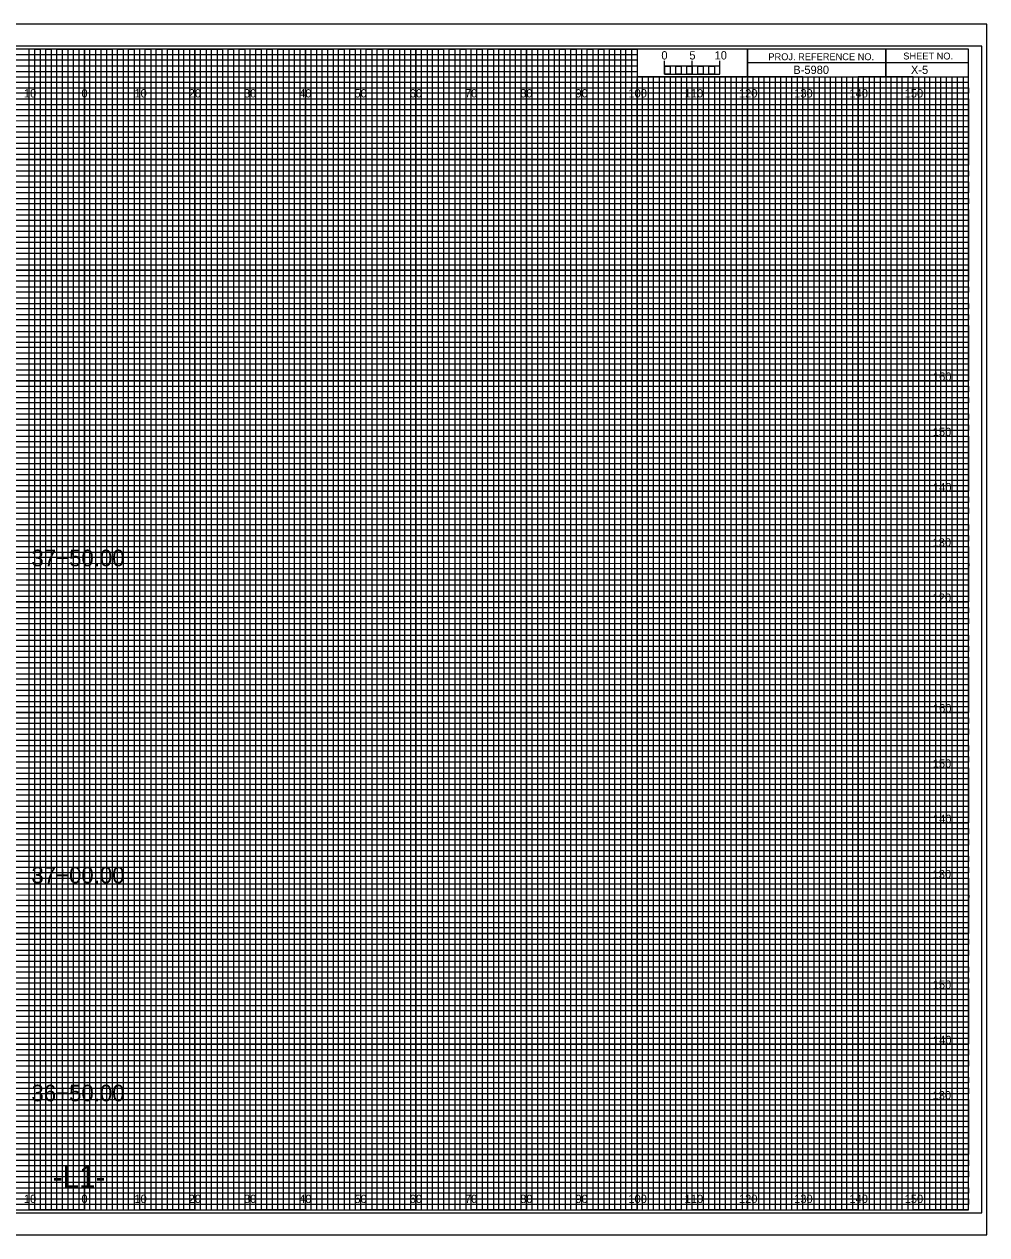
# Model space of a CAD drawing. Extents: x -13 to 323, y -5 to 3294.
# Drawn here: x 149.1 to 323.3, y 875.5 to 1094.5 of the extents above; entities that cross this region are included whole.
import ezdxf

# ---------------------------------------------------------------- set-up
doc = ezdxf.new("R2010")
doc.units = 0
for name, color, linetype in [('Prop XS Alignment Label', 7, 'Continuous'), ('Prop XS Bar Scale Labels', 7, 'Continuous'), ('Prop XS Elevation Labels', 7, 'Continuous'), ('Prop XS Offset Labels', 7, 'Continuous'), ('Prop XS Project Number', 7, 'Continuous'), ('Prop XS Sheet Number', 7, 'Continuous'), ('Prop XS Station Labels', 7, 'Continuous'), ('Sheet Cross Section CELL', 7, 'Continuous'), ('Sheet Cross Section Grid Major CELL', 7, 'Continuous'), ('Sheet Cross Section Grid Middle CELL', 7, 'Continuous'), ('Sheet Cross Section Grid Minor 1 CELL', 7, 'Continuous'), ('Sheet Cross Section Grid Minor 2 CELL', 7, 'Continuous'), ('Sheet Cross Section Scale CELL', 7, 'Continuous'), ('Sheet Cutting Line CELL', 7, 'Continuous'), ('Sheet DOT Grid CELL', 7, 'Continuous'), ('Sheet Plot Border Inside CELL', 7, 'Continuous'), ('Sheet Plot Border Outside CELL', 7, 'Continuous')]:
    doc.layers.add(name, color=color, linetype=linetype)

msp = doc.modelspace()

# ---------------------------------------------------------------- linework, layer by layer
at = {"layer": 'Sheet Cross Section CELL'}
for p, q in [((305, 1090), (305, 1085)), ((305, 1085), (305, 1090)), ((280, 1087.5), (280, 1085)), ((320, 1087.49), (280, 1087.49)), ((280, 1085), (320, 1085))]:
    msp.add_line(p, q, dxfattribs=at)
for points in [[(320, 1090), (0, 1090), (0, 880), (320, 880)], [(280, 1090), (260, 1090), (260, 1085.03), (280, 1085.03)], [(320, 1090), (280, 1090), (280, 1085), (320, 1085)]]:
    msp.add_lwpolyline(points, close=True, dxfattribs=at)
at = {"layer": 'Sheet Cross Section Grid Major CELL'}
for p, q in [((150, 1090), (140, 1090)), ((150, 880), (150, 1090)), ((170, 1090), (160, 1090)), ((160, 1090), (160, 880)), ((170, 880), (170, 1090)), ((190, 1090), (180, 1090)), ((180, 1090), (180, 880)), ((190, 880), (190, 1090)), ((210, 1090), (200, 1090)), ((200, 1090), (200, 880)), ((210, 880), (210, 1090)), ((230, 1090), (220, 1090)), ((220, 1090), (220, 880)), ((230, 880), (230, 1090)), ((250, 1090), (240, 1090)), ((240, 1090), (240, 880)), ((250, 880), (250, 1090)), ((260, 1090), (260, 880)), ((270, 880), (270, 1085)), ((290, 1085), (280, 1085)), ((280, 1085), (280, 880)), ((290, 880), (290, 1085)), ((310, 1085), (300, 1085)), ((300, 1085), (300, 880)), ((310, 880), (310, 1085)), ((160, 880), (150, 880)), ((180, 880), (170, 880)), ((200, 880), (190, 880)), ((220, 880), (210, 880)), ((240, 880), (230, 880)), ((260, 880), (250, 880)), ((280, 880), (270, 880)), ((300, 880), (290, 880)), ((320, 880), (310, 880)), ((320, 880), (320, 880))]:
    msp.add_line(p, q, dxfattribs=at)
for points in [[(0, 1080), (320, 1080), (320, 1070), (0, 1070)], [(0, 1060), (320, 1060), (320, 1050), (0, 1050)], [(0, 1040), (320, 1040), (320, 1030), (0, 1030)], [(0, 1020), (320, 1020), (320, 1010), (0, 1010)], [(0, 1000), (320, 1000), (320, 990), (0, 990)], [(0, 980), (320, 980), (320, 970), (0, 970)], [(0, 960), (320, 960), (320, 950), (0, 950)], [(0, 940), (320, 940), (320, 930), (0, 930)], [(0, 920), (320, 920), (320, 910), (0, 910)], [(0, 900), (320, 900), (320, 890), (0, 890)]]:
    msp.add_lwpolyline(points, dxfattribs=at)
at = {"layer": 'Sheet Cross Section Grid Middle CELL'}
for points in [[(145, 880), (155, 880), (155, 1090), (165, 1090), (165, 880), (175, 880), (175, 1090), (185, 1090), (185, 880), (195, 880), (195, 1090), (205, 1090), (205, 880), (215, 880), (215, 1090), (225, 1090), (225, 880), (235, 880), (235, 1090), (245, 1090), (245, 880), (255, 880), (255, 1090), (259.93, 1090), (260, 1090), (260, 1085), (264.99, 1085), (264.99, 880), (275, 880), (275, 1085), (285, 1085), (285, 880), (295, 880), (295, 1085), (305, 1085), (305, 880), (315, 880), (315, 1085)], [(0, 1085), (275, 1085)], [(0, 1065), (320, 1065), (320, 1075), (0, 1075)], [(0, 1045), (320, 1045), (320, 1055), (0, 1055)], [(0, 1025), (320, 1025), (320, 1035), (0, 1035)], [(0, 1005), (320, 1005), (320, 1015), (0, 1015)], [(0, 985), (320, 985), (320, 995), (0, 995)], [(0, 965), (320, 965), (320, 975), (0, 975)], [(0, 945), (320, 945), (320, 955), (0, 955)], [(0, 925), (320, 925), (320, 935), (0, 935)], [(0, 905), (320, 905), (320, 915), (0, 915)], [(0, 885), (320, 885), (320, 895), (0, 895)]]:
    msp.add_lwpolyline(points, dxfattribs=at)
at = {"layer": 'Sheet Cross Section Grid Minor 1 CELL'}
for p, q in [((0, 1089), (260, 1089)), ((260, 1089), (260, 1087.98)), ((260, 1087.98), (0, 1087.98)), ((0, 1087), (260, 1087)), ((260, 1087), (260, 1085.89)), ((260, 1085.89), (0, 1085.89)), ((0, 1084), (320, 1084))]:
    msp.add_line(p, q, dxfattribs=at)
for points in [[(0, 1083), (270, 1083), (320, 1083), (320, 1082), (0, 1082)], [(0, 1081), (320, 1081), (320, 1079), (0, 1079)], [(0, 1078), (320, 1078), (320, 1077), (0, 1076.98)], [(0, 1076), (320, 1076), (320, 1074), (0, 1074)], [(0, 1073), (320, 1073), (320, 1072), (0, 1072)], [(0, 1071), (320, 1071), (320, 1069), (0, 1069)], [(0, 1068), (320, 1068), (320, 1067), (0, 1067)], [(0, 1066), (320, 1066), (320, 1064), (0, 1064)], [(0, 1063), (320, 1063), (320, 1062), (0, 1062)], [(0, 1061), (320, 1061), (320, 1059), (0, 1059)], [(0, 1058), (320, 1058), (320, 1057), (0, 1057)], [(0, 1056), (320, 1056), (320, 1053.95), (320, 1053), (320, 1052), (0, 1052)], [(0, 1054), (320, 1054), (320, 1053), (0, 1053)], [(0, 1051), (320, 1051), (320, 1049), (0, 1049.03)], [(0, 1049.03), (320, 1049), (320, 1048), (0, 1048)], [(0, 1047), (320, 1047), (320, 1046), (0, 1046)], [(0, 1044), (320, 1044), (320, 1043), (0, 1043)], [(0, 1042), (320, 1042), (320, 1041), (0, 1041)], [(-0.07, 1038.89), (320, 1038.89), (320, 1037.88), (-0.07, 1037.88)], [(0, 1037), (320, 1037), (320, 1036), (0, 1036)], [(0, 1034), (320, 1034), (320, 1033), (0, 1033)], [(0, 1032), (320, 1032), (320, 1031), (0, 1031)], [(0, 1029), (320, 1029), (320, 1028), (0, 1028)], [(0, 1027), (320, 1027), (320, 1026), (0, 1026)], [(0, 1024), (320, 1024), (320, 1023), (0, 1023)], [(0, 1022), (320, 1022), (320, 1021), (0, 1021)], [(0, 1019), (320, 1019), (319.99, 1017.98), (0, 1018)], [(0, 1017), (320, 1017), (320, 1016), (0, 1016)], [(0, 1014), (320, 1014), (320, 1013), (0, 1013)], [(0, 1012), (320, 1012), (320, 1011), (0, 1011)], [(0, 1009), (320, 1009), (320, 1008), (0, 1008)], [(0, 1007), (320, 1007), (320, 1006), (0, 1006)], [(0, 1004), (320, 1004), (320, 1003), (0, 1003)], [(0, 1002), (320, 1002), (320, 1001), (0, 1001)], [(0, 999), (320, 999), (320, 998), (0, 998)], [(0, 996.99), (320.07, 996.91), (320, 996), (0, 996)], [(0, 994), (320, 994), (320, 993), (0, 993)], [(0, 992), (320, 992), (320, 991), (0, 991)], [(0, 989), (320, 989), (320, 988), (0, 988)], [(0, 987), (320, 987), (320, 986), (0, 986)], [(0, 984), (320, 984), (320, 983), (0, 983)], [(0, 982), (320, 982), (320, 981), (0, 981)], [(0, 979), (320, 979), (320, 978), (0, 978)], [(0, 977), (320, 977), (320, 976), (0, 976)], [(0, 974), (320, 974), (320, 973), (0, 973)], [(0, 972), (320, 972), (320, 971), (0, 971)], [(0, 969), (320, 969), (320, 968), (0, 968)], [(0, 967), (320, 967), (320, 966), (0, 966)], [(0, 964), (320, 964), (320, 963), (0, 963)], [(0, 962), (320, 962), (320, 961), (0, 961)], [(0, 959), (320, 959), (319.99, 957.98), (0, 958)], [(0, 957), (320, 957), (320, 956), (0, 956)], [(0, 954), (320, 954), (320, 953), (0, 953)], [(0, 952), (320, 952), (320, 951), (0, 951)], [(0, 949), (320, 949), (320, 948), (0, 948)], [(0, 947), (320, 947), (320, 946), (0, 946)], [(0, 944), (320, 944), (320, 943), (0, 943)], [(0, 942), (320, 942), (320, 941), (0, 941)], [(0, 939), (320, 939), (320, 938), (0, 938)], [(0, 936.99), (320.07, 936.91), (320, 936), (0, 936)], [(0, 934), (320, 934), (320, 933), (0, 933)], [(0, 932), (320, 932), (320, 931), (0, 931)], [(0, 929), (320, 929), (320, 928), (0, 928)], [(0, 927), (320, 927), (320, 926), (0, 926)], [(0, 924), (320, 924), (320, 923), (0, 923)], [(0, 922), (320, 922), (320, 921), (0, 921)], [(0, 919), (320, 919), (320, 918), (0, 918)], [(0, 917), (320, 917), (320, 916), (0, 916)], [(0, 914), (320, 914), (320, 913), (0, 913)], [(0, 912), (320, 912), (320, 911), (0, 911)], [(0, 909), (320, 909), (320, 908), (0, 908)], [(0, 907), (320, 907), (320, 906), (0, 906)], [(0, 904), (320, 904), (320, 903), (0, 903)], [(0, 902), (320, 902), (320, 901), (0, 901)], [(0, 899), (320, 899), (320, 898), (0, 898)], [(0, 897), (320, 897), (320, 896), (0, 896)], [(0, 894), (320, 894), (320, 893), (0, 893)], [(0, 892), (320, 892), (320, 891), (0, 891)], [(0, 889), (320, 889), (320, 888), (0, 888)], [(0, 887), (320, 887), (320, 886), (0, 886)], [(0, 884), (320, 884), (320, 883), (0, 883)], [(0, 882), (320, 882), (320, 881), (0, 881)]]:
    msp.add_lwpolyline(points, dxfattribs=at)
at = {"layer": 'Sheet Cross Section Grid Minor 2 CELL'}
for p, q in [((267, 1085), (266.01, 1085)), ((266.01, 1085), (266.01, 880)), ((267, 880), (267, 1085)), ((269, 1085), (268, 1085)), ((268, 1085), (268, 880)), ((269, 880), (269, 1085)), ((266.01, 880), (265, 880)), ((268, 880), (267, 880))]:
    msp.add_line(p, q, dxfattribs=at)
for points in [[(150, 880), (151, 880), (151, 1090), (152, 1090), (152, 880)], [(152, 880), (153, 880), (153, 1090), (154, 1090), (154, 880)], [(155, 880), (156, 880), (156, 1090), (157, 1090), (157, 880)], [(157, 880), (158, 880), (158, 1090), (159, 1090), (159, 880)], [(160, 880), (161, 880), (161, 1090), (162, 1090), (162, 880)], [(162, 880), (163, 880), (163, 1090), (164, 1090), (164, 880)], [(165, 880), (166, 880), (166, 1090), (167, 1090), (167, 880)], [(167, 880), (168, 880), (168, 1090), (169, 1090), (169, 880)], [(170, 880), (171, 880), (171, 1090), (172, 1090), (172, 880)], [(172, 880), (173, 880), (173, 1090), (174, 1090), (174, 880)], [(175, 880), (176, 880), (176, 1090), (177, 1090), (177, 880)], [(177, 880), (178, 880), (178, 1090), (179, 1090), (179, 880)], [(180, 880), (181, 880), (181, 1090), (182, 1090), (182, 880)], [(182, 880), (183, 880), (183, 1090), (184, 1090), (184, 880)], [(185, 880), (186, 880), (186, 1090), (187, 1090), (187, 880)], [(187, 880), (188, 880), (188, 1090), (189, 1090), (189, 880)], [(190, 880), (191, 880), (191, 1090), (192, 1090), (192, 880)], [(192, 880), (193, 880), (193, 1090), (194, 1090), (194, 880)], [(195, 880), (196, 880), (196, 1090), (197, 1090), (197, 880)], [(197, 880), (198, 880), (198, 1090), (199, 1090), (199, 880)], [(200, 880), (201, 880), (201, 1090), (202, 1090), (202, 880)], [(202, 880), (203, 880), (203, 1090), (204, 1090), (204, 880)], [(205, 880), (206, 880), (206, 1090), (207, 1090), (207, 880)], [(207, 880), (208, 880), (208, 1090), (209, 1090), (209, 880)], [(210, 880), (211, 880), (211, 1090), (212, 1090), (212, 880)], [(212, 880), (213, 880), (213, 1090), (214, 1090), (214, 880)], [(215, 880), (216, 880), (216, 1090), (217, 1090), (217, 880)], [(217, 880), (218, 880), (218, 1090), (219, 1090), (219, 880)], [(220, 880), (221, 880), (221, 1090), (222, 1090), (222, 880)], [(222, 880), (223, 880), (223, 1090), (224, 1090), (224, 880)], [(225, 880), (226, 880), (226, 1090), (227, 1090), (227, 880)], [(227, 880), (228, 880), (228, 1090), (229, 1090), (229, 880)], [(230, 880), (231, 880), (231, 1090), (232, 1090), (232, 880)], [(232, 880), (233, 880), (233, 1090), (234, 1090), (234, 880)], [(235, 880), (236, 880), (236, 1090), (237, 1090), (237, 880)], [(237, 880), (238, 880), (238, 1090), (239, 1090), (239, 880)], [(240, 880), (241, 880), (241, 1090), (242, 1090), (242, 880)], [(242, 880), (243, 880), (243, 1090), (244, 1090), (244, 880)], [(245, 880), (246, 880), (246, 1090), (247, 1090), (247, 880)], [(247, 880), (248, 880), (248, 1090), (249, 1090), (249, 880)], [(250, 880), (251, 880), (251, 1090), (252, 1090), (252, 880)], [(252, 880), (253, 880), (253, 1090), (254, 1090), (254, 880)], [(255, 880), (256, 880), (256, 1090), (257, 1090), (257, 880)], [(257, 880), (258, 880), (258, 1090), (259, 1090), (259, 880)], [(260, 880), (261, 880), (261, 1085), (262.02, 1085), (262.02, 880)], [(262, 880), (263, 880), (263, 1085), (263.99, 1085), (263.99, 880)], [(270, 880), (270.98, 880), (270.98, 1085), (272, 1085), (272, 880)], [(272, 880), (273, 880), (273, 1085), (274.05, 1085), (274.05, 880)], [(275, 880), (276, 880), (276, 1085), (277, 1085), (277, 880)], [(277, 880), (278, 880), (278, 1085), (279, 1085), (279, 880)], [(280, 880), (281, 880), (281, 1085), (282, 1085), (282, 880)], [(282, 880), (283, 880), (283, 1085), (284, 1085), (284, 880)], [(285, 880), (286, 880), (286, 1085), (287, 1085), (287, 880)], [(287, 880), (288, 880), (288, 1085), (289, 1085), (289, 880)], [(290, 880), (291, 880), (291, 1085), (292, 1085), (292, 880)], [(292, 880), (293, 880), (293, 1085), (294, 1085), (294, 880)], [(295, 880), (296, 880), (296, 1085), (297, 1085), (297, 880)], [(297, 880), (298, 880), (298, 1085), (299, 1085), (299, 880)], [(300, 880), (301, 880), (301, 1085), (302, 1085), (302, 880)], [(302, 880), (303, 880), (303, 1085), (304, 1085), (304, 880)], [(305, 880), (306, 880), (306, 1085), (307, 1085), (307, 880)], [(307, 880), (308, 880), (308, 1085), (309, 1085), (309, 880)], [(310, 880), (311, 880), (311, 1085), (312, 1085), (312, 880)], [(312, 880), (313, 880), (313, 1085), (314, 1085), (314, 880)], [(315, 880), (316, 880), (316, 1085), (317, 1085), (317, 880)], [(317, 880), (318, 880), (318, 1085), (319, 1085), (319, 880)]]:
    msp.add_lwpolyline(points, dxfattribs=at)
at = {"layer": 'Sheet Cross Section Scale CELL'}
for p, q in [((265, 1085.49), (265, 1087.9)), ((265, 1086.9), (265, 1087.9)), ((270, 1085.49), (270, 1087.9)), ((275, 1085.49), (275, 1087.9)), ((275, 1086.9), (275, 1087.9))]:
    msp.add_line(p, q, dxfattribs=at)
for points in [[(275, 1086.9), (265, 1086.9), (265, 1085.49), (275, 1085.49)], [(265, 1086.9), (266, 1086.9), (266, 1085.49), (265, 1085.49)], [(267, 1086.9), (268, 1086.9), (268, 1085.49), (267, 1085.49)], [(269, 1086.9), (270, 1086.9), (270, 1085.49), (269, 1085.49)], [(271, 1086.9), (272, 1086.9), (272, 1085.49), (271, 1085.49)], [(273, 1086.9), (274, 1086.9), (274, 1085.49), (273, 1085.49)]]:
    msp.add_lwpolyline(points, close=True, dxfattribs=at)
at = {"layer": 'Sheet Cutting Line CELL'}
for p, q in [((323.3, 1094.5), (-13.4, 1094.5)), ((-13.4, 875.5), (323.3, 875.5))]:
    msp.add_line(p, q, dxfattribs=at)
at = {"layer": 'Sheet DOT Grid CELL'}
for p, q in [((150, 880), (150, 1090)), ((160, 880), (160, 1090)), ((170, 880), (170, 1090)), ((180, 880), (180, 1090)), ((190, 880), (190, 1090)), ((200, 880), (200, 1090)), ((210, 880), (210, 1090)), ((220, 880), (220, 1090)), ((230, 880), (230, 1090)), ((240, 880), (240, 1090)), ((250, 880), (250, 1090)), ((260, 880), (260, 1084.69)), ((270, 880), (270, 1084.69)), ((280, 880), (280, 1084.69)), ((290, 880), (290, 1084.69)), ((300, 880), (300, 1084.69)), ((310, 880), (310, 1084.69)), ((0, 1080), (320, 1080)), ((0, 1070), (320, 1070)), ((0, 1060), (320, 1060)), ((0, 1050), (320, 1050)), ((0, 1040), (320, 1040)), ((0, 1030), (320, 1030)), ((0, 1020), (320, 1020)), ((0, 1010), (320, 1010)), ((0, 1000), (320, 1000)), ((0, 990), (320, 990)), ((0, 980), (320, 980)), ((0, 970), (320, 970)), ((0, 960), (320, 960)), ((0, 950), (320, 950)), ((0, 940), (320, 940)), ((0, 930), (320, 930)), ((0, 920), (320, 920)), ((0, 910), (320, 910)), ((0, 900), (320, 900)), ((0, 890), (320, 890))]:
    msp.add_line(p, q, dxfattribs=at)
at = {"layer": 'Sheet Plot Border Inside CELL'}
msp.add_lwpolyline([(-10.8, 879.5), (322.4, 879.5), (322.4, 1090.5), (-10.8, 1090.5)], close=True, dxfattribs=at)
at = {"layer": 'Sheet Plot Border Outside CELL'}
msp.add_lwpolyline([(-13.4, 875.5), (323.3, 875.5), (323.3, 1094.5), (-13.4, 1094.5)], close=True, dxfattribs=at)

# ---------------------------------------------------------------- texts
at = {"layer": 'Prop XS Alignment Label'}
msp.add_text('-L1-', height=4, dxfattribs=at).set_placement((154.28, 884))
at = {"layer": 'Prop XS Bar Scale Labels'}
for s, p in [('5', (269.47, 1088.12)), ('10', (274.04, 1088.12))]:
    msp.add_text(s, height=1.5, dxfattribs=at).set_placement(p)
at = {"layer": 'Prop XS Elevation Labels'}
for s, p in [('160', (313.57, 1030)), ('150', (313.52, 1020)), ('140', (313.57, 1010)), ('130', (313.49, 1000)), ('120', (313.5, 990)), ('160', (313.57, 970)), ('150', (313.52, 960)), ('140', (313.57, 950)), ('130', (313.49, 940)), ('150', (313.52, 920)), ('140', (313.57, 910)), ('130', (313.49, 900))]:
    msp.add_text(s, height=1.5, dxfattribs=at).set_placement(p)
at = {"layer": 'Prop XS Offset Labels'}
for s, p in [('10', (149.04, 1081.25)), ('0', (159.45, 1081.25)), ('0', (159.45, 1081.25)), ('10', (169.04, 1081.25)), ('20', (178.86, 1081.25)), ('30', (188.86, 1081.25)), ('40', (198.86, 1081.25)), ('50', (208.86, 1081.25)), ('60', (218.86, 1081.25)), ('70', (228.86, 1081.25)), ('80', (238.86, 1081.25)), ('90', (248.86, 1081.25)), ('100', (258.44, 1081.25)), ('110', (268.62, 1081.25)), ('120', (278.44, 1081.25)), ('130', (288.44, 1081.25)), ('140', (298.44, 1081.25)), ('150', (308.44, 1081.25)), ('10', (149.04, 881.25)), ('0', (159.45, 881.25)), ('0', (159.45, 881.25)), ('10', (169.04, 881.25)), ('20', (178.86, 881.25)), ('30', (188.86, 881.25)), ('40', (198.86, 881.25)), ('50', (208.86, 881.25)), ('60', (218.86, 881.25)), ('70', (228.86, 881.25)), ('80', (238.86, 881.25)), ('90', (248.86, 881.25)), ('100', (258.44, 881.25)), ('110', (268.62, 881.25)), ('120', (278.44, 881.25)), ('130', (288.44, 881.25)), ('140', (298.44, 881.25)), ('150', (308.44, 881.25))]:
    msp.add_text(s, height=1.5, dxfattribs=at).set_placement(p)
at = {"layer": 'Prop XS Project Number'}
msp.add_text('B-5980', height=1.5, dxfattribs=at).set_placement((288.28, 1085.5))
at = {"layer": 'Prop XS Sheet Number'}
msp.add_text('X-5', height=1.5, dxfattribs=at).set_placement((309.57, 1085.5))
at = {"layer": 'Prop XS Station Labels'}
for s, p in [('37+50.00', (150.41, 996.44)), ('37+00.00', (150.41, 939.08)), ('36+50.00', (150.41, 899.65))]:
    msp.add_text(s, height=3, dxfattribs=at).set_placement(p)
at = {"layer": 'Sheet Cross Section CELL'}
for s, p in [('PROJ. REFERENCE NO.', (283.77, 1087.99)), ('SHEET NO.', (308.19, 1088.12))]:
    msp.add_text(s, height=1.25, dxfattribs=at).set_placement(p)
at = {"layer": 'Sheet Cross Section Scale CELL'}
msp.add_text('0', height=1.5, dxfattribs=at).set_placement((264.41, 1088.12))

doc.saveas('drawing.dxf')
